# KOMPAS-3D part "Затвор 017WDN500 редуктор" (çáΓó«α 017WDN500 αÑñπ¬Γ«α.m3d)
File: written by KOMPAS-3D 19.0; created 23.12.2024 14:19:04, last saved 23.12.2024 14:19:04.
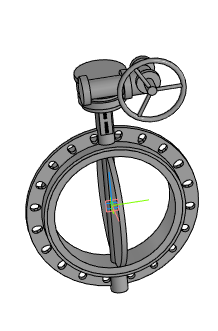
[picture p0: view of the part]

Document properties: Автор: Евгений; Полное имя файла: ..\Затвор 017WDN500 редуктор.a3d

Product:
- Part/product: Затвор 017WDN500 редуктор
    Масса: 187.221

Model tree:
1. Операция без истории:1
